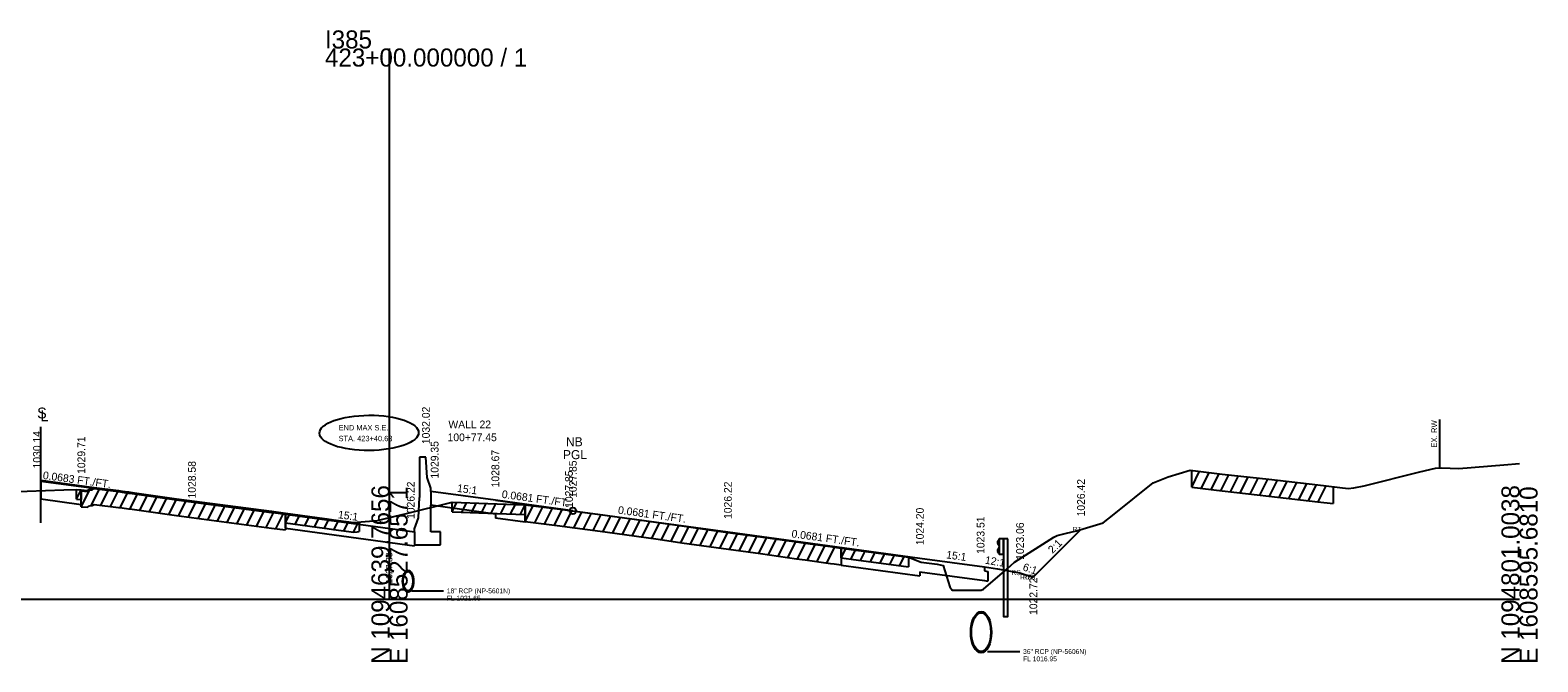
# Model space of a CAD drawing. Extents: x -26 to 1614813, y -18 to 1100051.
# Drawn here: x 4119.3 to 4352.8, y 9490.3 to 9588.2 of the extents above; entities that cross this region are included whole.
import ezdxf

# ---------------------------------------------------------------- set-up
doc = ezdxf.new("R2010")
doc.units = 0
for name, color, linetype in [('RD_EX_Misc', 7, 'Continuous'), ('RD_GPK_XS_Cell', 7, 'Continuous'), ('RD_HY_TX1', 7, 'Continuous'), ('RD_Sketch1', 7, 'Continuous'), ('RD_Sketch10', 7, 'Continuous'), ('RD_XS_Base', 7, 'Continuous'), ('RD_XS_CurbFront', 7, 'Continuous'), ('RD_XS_EarthShd', 7, 'Continuous'), ('RD_XS_ExGround', 7, 'Continuous'), ('RD_XS_ExPaveRet', 7, 'Continuous'), ('RD_XS_ExRW', 7, 'Continuous'), ('RD_XS_GR', 7, 'Continuous'), ('RD_XS_MedBbase', 7, 'Continuous'), ('RD_XS_MedBWall', 7, 'Continuous'), ('RD_XS_Milling', 7, 'Continuous'), ('RD_XS_Pave', 7, 'Continuous'), ('RD_XS_PaveOvlay', 7, 'Continuous'), ('RD_XS_PaveShd', 7, 'Continuous'), ('RD_XS_Pipe', 7, 'Continuous'), ('RD_XS_TieSlope', 7, 'Continuous'), ('RD_XS_TX_Elev_PR', 7, 'Continuous'), ('RD_XS_TX_MatchLine', 7, 'Continuous'), ('RD_XS_TX_Misc', 7, 'Continuous'), ('RD_XS_TX_Notes', 7, 'Continuous'), ('RD_XS_TX_ShdSlope', 7, 'Continuous'), ('RD_XS_TX_Slope', 7, 'Continuous')]:
    doc.layers.add(name, color=color, linetype=linetype)

msp = doc.modelspace()

# ---------------------------------------------------------------- linework, layer by layer
at = {"layer": 'RD_EX_Misc'}
for p, q in [((4126.52, 9515.51), (4126.52, 9517.01)), ((4126.52, 9515.51), (4127.27, 9515.44)), ((4127.27, 9516.94), (4127.27, 9515.44)), ((4127.27, 9515.44), (4127.27, 9515.44)), ((4184.7, 9513.57), (4184.7, 9515.07)), ((4158.87, 9511.85), (4158.87, 9513.35)), ((4184.7, 9513.57), (4190.23, 9513.35)), ((4190.23, 9513.35), (4196.01, 9513.15)), ((4196.01, 9514.65), (4196.01, 9513.15)), ((4158.87, 9511.85), (4164.93, 9511.02)), ((4158.87, 9511.85), (4158.87, 9511.85)), ((4164.93, 9511.02), (4165.32, 9510.96)), ((4165.32, 9510.96), (4166.34, 9510.82)), ((4166.34, 9510.82), (4169.48, 9510.39)), ((4169.48, 9510.39), (4170, 9510.45)), ((4170, 9510.45), (4170.31, 9510.48)), ((4170.31, 9511.98), (4170.31, 9510.48)), ((4244.95, 9506.43), (4244.95, 9507.93)), ((4244.95, 9506.43), (4246.49, 9506.22)), ((4244.95, 9506.43), (4244.95, 9506.43)), ((4246.49, 9506.22), (4255.36, 9505.01)), ((4255.36, 9506.51), (4255.36, 9505.01)), ((4255.36, 9505.01), (4255.36, 9505.01))]:
    msp.add_line(p, q, dxfattribs=at)
at = {"layer": 'RD_GPK_XS_Cell'}
for p, q in [((4175, 9500), (4175, 9585.33)), ((4000, 9500), (4175, 9500)), ((4175, 9500), (4350, 9500))]:
    msp.add_line(p, q, dxfattribs=at)
at = {"layer": 'RD_Sketch1'}
for p, q in [((4126.52, 9515.51), (4127.24, 9516.95)), ((4184.7, 9513.57), (4185.44, 9515.04)), ((4186.21, 9513.51), (4186.95, 9514.98)), ((4187.72, 9513.45), (4188.46, 9514.92)), ((4158.87, 9511.85), (4159.58, 9513.26)), ((4160.38, 9511.64), (4161.09, 9513.05)), ((4161.89, 9511.44), (4162.6, 9512.84)), ((4163.4, 9511.23), (4164.1, 9512.63)), ((4189.23, 9513.39), (4189.97, 9514.86)), ((4190.74, 9513.33), (4191.48, 9514.81)), ((4192.24, 9513.28), (4192.98, 9514.76)), ((4193.75, 9513.23), (4194.49, 9514.7)), ((4195.26, 9513.18), (4196, 9514.65)), ((4164.91, 9511.02), (4165.61, 9512.42)), ((4166.41, 9510.81), (4167.12, 9512.21)), ((4167.92, 9510.6), (4168.63, 9512)), ((4169.43, 9510.39), (4170.22, 9511.97)), ((4244.95, 9506.43), (4245.65, 9507.83)), ((4246.45, 9506.23), (4247.16, 9507.63)), ((4247.96, 9506.02), (4248.67, 9507.43)), ((4249.47, 9505.82), (4250.18, 9507.22)), ((4250.98, 9505.61), (4251.68, 9507.01)), ((4252.49, 9505.4), (4253.19, 9506.81)), ((4253.99, 9505.2), (4254.7, 9506.6))]:
    msp.add_line(p, q, dxfattribs=at)
at = {"layer": 'RD_Sketch10'}
for p, q in [((4121, 9518.45), (4145, 9515.17)), ((4145, 9515.17), (4157, 9513.53)), ((4191.39, 9515.34), (4203.39, 9513.71)), ((4203.39, 9513.71), (4227.4, 9510.44)), ((4227.4, 9510.44), (4251.4, 9507.17))]:
    msp.add_line(p, q, dxfattribs=at)
at = {"layer": 'RD_XS_Base'}
for p, q in [((4121, 9518.27), (4121, 9515.5)), ((4127.27, 9514.64), (4121, 9515.5)), ((4158.87, 9511.03), (4158.87, 9513.17)), ((4191.39, 9513.21), (4181.39, 9514.57)), ((4191.39, 9513.21), (4191.39, 9512.57)), ((4196.01, 9511.94), (4191.39, 9512.57)), ((4196.01, 9514.65), (4200.98, 9514.01)), ((4196.01, 9514.65), (4196.01, 9511.94)), ((4200.98, 9514.01), (4203.39, 9513.69)), ((4203.39, 9513.69), (4208.38, 9513.04)), ((4208.38, 9513.04), (4216.61, 9511.89)), ((4158.87, 9511.03), (4178.89, 9508.3)), ((4216.61, 9511.89), (4220.28, 9511.36)), ((4220.28, 9511.36), (4225.61, 9510.61)), ((4225.61, 9510.61), (4227.4, 9510.37)), ((4227.4, 9510.37), (4232.44, 9509.67)), ((4232.44, 9509.67), (4238.02, 9508.88)), ((4238.02, 9508.88), (4239.36, 9508.7)), ((4239.36, 9508.7), (4243.32, 9508.16)), ((4243.32, 9508.16), (4243.84, 9508.09)), ((4243.84, 9508.09), (4244.95, 9507.93)), ((4244.95, 9507.93), (4244.95, 9505.27)), ((4244.95, 9505.27), (4257.14, 9503.61)), ((4257.14, 9504.26), (4267.14, 9502.89)), ((4257.14, 9504.26), (4257.14, 9503.61)), ((4267.14, 9505.03), (4267.14, 9504.39)), ((4267.14, 9504.39), (4267.64, 9504.32)), ((4267.64, 9504.32), (4267.64, 9502.82)), ((4267.14, 9502.89), (4267.64, 9502.82))]:
    msp.add_line(p, q, dxfattribs=at)
at = {"layer": 'RD_XS_CurbFront'}
for p, q in [((4181.39, 9516.71), (4181.39, 9514.57)), ((4178.89, 9510.44), (4178.89, 9508.44))]:
    msp.add_line(p, q, dxfattribs=at)
at = {"layer": 'RD_XS_EarthShd'}
for p, q in [((4267.14, 9505.03), (4269.14, 9504.7)), ((4269.14, 9504.7), (4272.64, 9504.11))]:
    msp.add_line(p, q, dxfattribs=at)
at = {"layer": 'RD_XS_ExGround'}
msp.add_lwpolyline([(4116.06, 9516.66), (4124.54, 9516.94), (4126.52, 9517.01), (4127.27, 9516.94), (4128.22, 9516.85), (4128.56, 9517.07), (4128.97, 9517.12), (4129.26, 9517.31), (4133.03, 9516.84), (4133.61, 9516.77), (4134.57, 9516.63), (4135.14, 9516.54), (4142.02, 9515.56), (4156.71, 9513.63), (4158.87, 9513.35), (4164.93, 9512.52), (4165.32, 9512.46), (4166.34, 9512.32), (4169.48, 9511.89), (4170, 9511.95), (4173.13, 9512.21), (4175, 9512.67), (4177.41, 9513.26), (4184.69, 9515.07), (4190.23, 9514.85), (4196.01, 9514.65), (4200.98, 9514.01), (4208.38, 9513.04), (4216.61, 9511.89), (4220.28, 9511.36), (4225.61, 9510.61), (4232.44, 9509.67), (4238.02, 9508.88), (4239.36, 9508.7), (4243.32, 9508.16), (4243.84, 9508.09), (4244.95, 9507.93), (4246.49, 9507.72), (4255.36, 9506.51), (4257.31, 9505.73), (4259.82, 9505.44), (4260.76, 9505.22), (4261.75, 9501.94), (4262.13, 9501.43), (4266.63, 9501.43), (4266.97, 9501.55), (4270.68, 9504.73), (4271.8, 9505.74), (4277.9, 9509.62), (4278.39, 9509.89), (4279.86, 9510.22), (4281.38, 9510.63), (4285.5, 9511.83), (4287.25, 9513.2), (4293.28, 9518.02), (4295.57, 9518.95), (4299.02, 9520.01), (4303.97, 9519.38), (4311.18, 9518.59), (4318.75, 9517.71), (4323.48, 9517.16), (4324.36, 9517.29), (4325.96, 9517.57), (4334.56, 9519.72), (4336.98, 9520.3), (4337.91, 9520.38), (4340.59, 9520.24), (4347.57, 9520.85), (4350, 9521.05)], dxfattribs=at)
at = {"layer": 'RD_XS_ExPaveRet'}
for p, q in [((4299.23, 9517.38), (4299.23, 9519.98)), ((4299.23, 9517.38), (4300.46, 9519.83)), ((4300.74, 9517.19), (4301.96, 9519.64)), ((4299.23, 9517.38), (4303.97, 9516.78)), ((4302.24, 9517), (4303.47, 9519.45)), ((4303.75, 9516.81), (4304.99, 9519.27)), ((4305.26, 9516.64), (4306.49, 9519.11)), ((4306.76, 9516.48), (4308, 9518.94)), ((4308.27, 9516.31), (4309.51, 9518.78)), ((4309.78, 9516.15), (4311.01, 9518.61)), ((4311.28, 9515.98), (4312.52, 9518.44)), ((4312.79, 9515.8), (4314.02, 9518.26)), ((4314.3, 9515.63), (4315.53, 9518.08)), ((4315.8, 9515.45), (4317.04, 9517.91)), ((4317.31, 9515.28), (4318.55, 9517.73)), ((4318.82, 9515.1), (4320.05, 9517.56)), ((4321.15, 9517.43), (4321.15, 9514.83)), ((4127.27, 9514.34), (4128.65, 9517.08)), ((4127.27, 9514.34), (4127.27, 9516.94)), ((4128.78, 9514.5), (4130.14, 9517.2)), ((4130.29, 9514.58), (4131.52, 9517.03)), ((4131.8, 9514.4), (4133.02, 9516.84)), ((4133.3, 9514.21), (4134.52, 9516.63)), ((4134.81, 9513.99), (4136.03, 9516.42)), ((4136.32, 9513.78), (4137.53, 9516.2)), ((4137.82, 9513.56), (4139.04, 9515.99)), ((4139.33, 9513.34), (4140.55, 9515.77)), ((4140.84, 9513.13), (4142.06, 9515.56)), ((4142.34, 9512.92), (4143.57, 9515.36)), ((4143.85, 9512.72), (4145.08, 9515.16)), ((4145.36, 9512.52), (4146.58, 9514.96)), ((4303.97, 9516.78), (4311.18, 9515.99)), ((4311.18, 9515.99), (4318.75, 9515.11)), ((4318.75, 9515.11), (4321.15, 9514.83)), ((4127.27, 9514.34), (4128.22, 9514.25)), ((4128.22, 9514.25), (4128.56, 9514.47)), ((4128.56, 9514.47), (4128.97, 9514.52)), ((4128.97, 9514.52), (4129.26, 9514.71)), ((4129.26, 9514.71), (4133.03, 9514.24)), ((4133.03, 9514.24), (4133.61, 9514.17)), ((4133.61, 9514.17), (4134.57, 9514.03)), ((4134.57, 9514.03), (4135.14, 9513.94)), ((4135.14, 9513.94), (4142.02, 9512.96)), ((4142.02, 9512.96), (4156.71, 9511.03)), ((4146.86, 9512.32), (4148.09, 9514.76)), ((4148.37, 9512.13), (4149.6, 9514.56)), ((4149.88, 9511.93), (4151.1, 9514.37)), ((4151.38, 9511.73), (4152.61, 9514.17)), ((4152.89, 9511.53), (4154.12, 9513.97)), ((4154.4, 9511.33), (4155.62, 9513.77)), ((4155.91, 9511.14), (4157.13, 9513.58)), ((4157.41, 9510.94), (4158.64, 9513.38)), ((4158.87, 9513.35), (4158.87, 9510.75)), ((4196.01, 9512.05), (4196.01, 9514.65)), ((4196.01, 9512.05), (4197.24, 9514.49)), ((4197.52, 9511.86), (4198.74, 9514.3)), ((4199.02, 9511.66), (4200.25, 9514.1)), ((4200.53, 9511.47), (4201.76, 9513.91)), ((4202.04, 9511.27), (4203.26, 9513.71)), ((4203.54, 9511.07), (4204.77, 9513.51)), ((4205.05, 9510.88), (4206.28, 9513.32)), ((4206.56, 9510.68), (4207.78, 9513.12)), ((4208.07, 9510.49), (4209.29, 9512.92)), ((4209.57, 9510.28), (4210.79, 9512.71)), ((4156.71, 9511.03), (4158.87, 9510.75)), ((4196.01, 9512.05), (4200.98, 9511.41)), ((4200.98, 9511.41), (4208.38, 9510.44)), ((4208.38, 9510.44), (4216.61, 9509.29)), ((4211.08, 9510.07), (4212.3, 9512.49)), ((4212.59, 9509.85), (4213.81, 9512.28)), ((4214.09, 9509.64), (4215.31, 9512.07)), ((4215.6, 9509.43), (4216.82, 9511.86)), ((4217.11, 9509.22), (4218.32, 9511.64)), ((4218.61, 9509), (4219.83, 9511.43)), ((4220.12, 9508.78), (4221.34, 9511.21)), ((4221.63, 9508.57), (4222.85, 9511)), ((4223.13, 9508.36), (4224.35, 9510.79)), ((4224.64, 9508.15), (4225.86, 9510.58)), ((4226.15, 9507.94), (4227.37, 9510.37)), ((4216.61, 9509.29), (4220.28, 9508.76)), ((4220.28, 9508.76), (4225.61, 9508.01)), ((4225.61, 9508.01), (4232.44, 9507.07)), ((4227.65, 9507.73), (4228.88, 9510.16)), ((4229.16, 9507.52), (4230.38, 9509.95)), ((4230.67, 9507.31), (4231.89, 9509.74)), ((4232.18, 9507.1), (4233.4, 9509.53)), ((4233.68, 9506.89), (4234.9, 9509.32)), ((4235.19, 9506.68), (4236.41, 9509.11)), ((4236.7, 9506.47), (4237.92, 9508.9)), ((4238.2, 9506.26), (4239.43, 9508.69)), ((4239.71, 9506.05), (4240.93, 9508.48)), ((4241.22, 9505.84), (4242.44, 9508.28)), ((4242.72, 9505.64), (4243.95, 9508.07)), ((4244.95, 9507.93), (4244.95, 9505.33)), ((4232.44, 9507.07), (4238.02, 9506.28)), ((4238.02, 9506.28), (4239.36, 9506.1)), ((4239.36, 9506.1), (4243.32, 9505.56)), ((4243.32, 9505.56), (4243.84, 9505.49)), ((4243.84, 9505.49), (4244.95, 9505.33))]:
    msp.add_line(p, q, dxfattribs=at)
at = {"layer": 'RD_XS_ExRW'}
msp.add_line((4337.6, 9527.87), (4337.6, 9520.36), dxfattribs=at)
at = {"layer": 'RD_XS_GR'}
for p, q in [((4269.17, 9508.93), (4269.32, 9509.16)), ((4269.17, 9508.69), (4269.38, 9508.37)), ((4269.17, 9507.66), (4269.38, 9507.98)), ((4269.41, 9509.2), (4269.33, 9509.17)), ((4269.17, 9507.41), (4269.32, 9507.19)), ((4269.41, 9507.15), (4269.33, 9507.18))]:
    msp.add_line(p, q, dxfattribs=at)
for points in [[(4270.08, 9509.34), (4269.41, 9509.34), (4269.41, 9507.01), (4270.08, 9507.01)], [(4270.74, 9509.34), (4270.08, 9509.34), (4270.08, 9497.34), (4270.74, 9497.34)]]:
    msp.add_lwpolyline(points, close=True, dxfattribs=at)
for centre, major_axis, start_param, end_param in [((4269.22, 9508.81), (0, -0.156), 3.787686, 5.637551), ((4269.34, 9509.11), (0, 0.0626), 0.174533, 0.6458), ((4269.33, 9508.25), (0, 0.156), 4.712389, 5.637385), ((4269.33, 9508.1), (0, -0.156), 0.6458, 1.570796), ((4269.22, 9507.54), (0, -0.156), 3.787227, 5.637092), ((4269.34, 9507.24), (0, -0.0626), 5.637385, 6.108652)]:
    msp.add_ellipse(centre, major_axis=major_axis, ratio=0.5, start_param=start_param, end_param=end_param, dxfattribs=at)
at = {"layer": 'RD_XS_MedBbase'}
for p, q in [((4181.39, 9510.44), (4181.39, 9514.57)), ((4182.89, 9510.44), (4181.39, 9510.44)), ((4182.89, 9508.44), (4182.89, 9510.44)), ((4178.89, 9508.44), (4182.89, 9508.44)), ((4178.89, 9508.44), (4178.89, 9508.3))]:
    msp.add_line(p, q, dxfattribs=at)
at = {"layer": 'RD_XS_MedBWall'}
for p, q in [((4179.64, 9522.04), (4179.64, 9515.77)), ((4180.64, 9522.04), (4179.64, 9522.04)), ((4180.81, 9518.87), (4180.64, 9522.04)), ((4181.39, 9517.21), (4180.81, 9518.87)), ((4181.39, 9516.71), (4181.39, 9517.21)), ((4179.48, 9512.6), (4179.64, 9515.77)), ((4178.89, 9510.94), (4179.48, 9512.6)), ((4178.89, 9510.44), (4178.89, 9510.94))]:
    msp.add_line(p, q, dxfattribs=at)
at = {"layer": 'RD_XS_Milling'}
for p, q in [((4127.27, 9516.94), (4127.27, 9516.78)), ((4127.27, 9516.78), (4128.22, 9516.69)), ((4128.22, 9516.69), (4128.56, 9516.91)), ((4128.56, 9516.91), (4128.97, 9516.96)), ((4128.97, 9516.96), (4129.26, 9517.15)), ((4129.26, 9517.15), (4133.03, 9516.68)), ((4133.03, 9516.68), (4133.61, 9516.6)), ((4133.61, 9516.6), (4134.57, 9516.46)), ((4134.57, 9516.46), (4135.14, 9516.38)), ((4135.14, 9516.38), (4142.02, 9515.39)), ((4142.02, 9515.39), (4145, 9515)), ((4145, 9515.17), (4145, 9515)), ((4145, 9515), (4156.71, 9513.46)), ((4156.71, 9513.46), (4157, 9513.43)), ((4157, 9513.59), (4157, 9513.43))]:
    msp.add_line(p, q, dxfattribs=at)
at = {"layer": 'RD_XS_Pave'}
for p, q in [((4127.27, 9517.42), (4121, 9518.27)), ((4129.26, 9517.15), (4127.27, 9517.42)), ((4203.39, 9513.71), (4191.39, 9515.34)), ((4203.39, 9513.71), (4227.4, 9510.44)), ((4227.4, 9510.44), (4257.14, 9506.39))]:
    msp.add_line(p, q, dxfattribs=at)
at = {"layer": 'RD_XS_PaveOvlay'}
for p, q in [((4128.97, 9517.12), (4129.26, 9517.31)), ((4129.26, 9517.31), (4133.03, 9516.84)), ((4127.27, 9516.94), (4128.22, 9516.85)), ((4127.27, 9516.94), (4127.27, 9516.78)), ((4128.22, 9516.85), (4128.56, 9517.07)), ((4128.56, 9517.07), (4128.97, 9517.12)), ((4133.03, 9516.84), (4133.61, 9516.77)), ((4133.61, 9516.77), (4134.57, 9516.63)), ((4134.57, 9516.63), (4135.14, 9516.54)), ((4135.14, 9516.54), (4142.02, 9515.56)), ((4142.02, 9515.56), (4145, 9515.17)), ((4145, 9515.17), (4156.71, 9513.63)), ((4156.71, 9513.63), (4157, 9513.59)), ((4157, 9513.59), (4157, 9513.43))]:
    msp.add_line(p, q, dxfattribs=at)
at = {"layer": 'RD_XS_PaveShd'}
for p, q in [((4191.39, 9515.34), (4181.39, 9516.71)), ((4157, 9513.43), (4178.89, 9510.44)), ((4257.14, 9506.39), (4267.14, 9505.03))]:
    msp.add_line(p, q, dxfattribs=at)
at = {"layer": 'RD_XS_Pipe'}
for p, q in [((4178.38, 9501.3), (4183.38, 9501.3)), ((4267.62, 9491.9), (4272.62, 9491.9))]:
    msp.add_line(p, q, dxfattribs=at)
for centre, major_axis in [((4177.88, 9502.8), (0, 1.7)), ((4177.88, 9502.8), (0, 1.5)), ((4266.62, 9494.9), (0, 3.2)), ((4266.62, 9494.9), (0, 3))]:
    msp.add_ellipse(centre, major_axis=major_axis, ratio=0.5, dxfattribs=at)
at = {"layer": 'RD_XS_TieSlope'}
for p, q in [((4274.66, 9503.44), (4282.09, 9510.84)), ((4272.64, 9504.11), (4274.66, 9503.44))]:
    msp.add_line(p, q, dxfattribs=at)
at = {"layer": 'RD_XS_TX_MatchLine'}
for p, q in [((4121, 9516.82), (4121, 9526.71)), ((4121, 9511.82), (4121, 9516.82))]:
    msp.add_line(p, q, dxfattribs=at)
at = {"layer": 'RD_XS_TX_Misc'}
msp.add_circle((4203.39, 9513.71), 0.5, dxfattribs=at)
at = {"layer": 'RD_XS_TX_Notes'}
msp.add_ellipse((4171.83, 9525.78), major_axis=(7.68, 0.05), ratio=0.355189, dxfattribs=at)

# ---------------------------------------------------------------- texts
at = {"layer": 'RD_GPK_XS_Cell'}
for s, p in [('I385', (4165, 9585.33)), ('423+00.000000 / 1', (4165, 9582.53))]:
    msp.add_text(s, height=2.8, dxfattribs=at).set_placement(p)
for s, p in [('N 1094639.7656', (4175, 9490)), ('E 1608527.6571', (4177.8, 9490)), ('N 1094801.0038', (4350, 9490)), ('E 1608595.6810', (4352.8, 9490))]:
    msp.add_text(s, height=2.8, rotation=90, dxfattribs=at).set_placement(p)
at = {"layer": 'RD_HY_TX1'}
for s, p in [('RT', (4280.78, 9510.46)), ('RS', (4271.33, 9503.74)), ('RD2', (4272.67, 9503.07)), ('RD1', (4273.05, 9503.07))]:
    msp.add_text(s, height=0.75, dxfattribs=at).set_placement(p)
at = {"layer": 'RD_Sketch10'}
for s, p in [(' 1028.58', (4145, 9515.17)), (' 1027.85', (4203.39, 9513.71))]:
    msp.add_text(s, height=1.2, rotation=90, dxfattribs=at).set_placement(p)
at = {"layer": 'RD_XS_ExGround'}
msp.add_text('1027.33', height=1, rotation=90, dxfattribs=at).set_placement((4175.44, 9502.43))
at = {"layer": 'RD_XS_ExRW'}
msp.add_text('EX. RW', height=0.9, rotation=90, dxfattribs=at).set_placement((4337.24, 9523.47))
at = {"layer": 'RD_XS_Pipe'}
for s, p in [('18" RCP (NP-5601N)', (4183.88, 9500.93)), ('FL 1021.65', (4183.88, 9499.8)), ('36" RCP (NP-5606N)', (4273.12, 9491.53)), ('FL 1016.95', (4273.12, 9490.4))]:
    msp.add_text(s, height=0.75, dxfattribs=at).set_placement(p)
at = {"layer": 'RD_XS_TX_Elev_PR'}
for s, p in [('1032.02', (4181.24, 9524.04)), ('1030.14', (4121, 9520.27)), ('1029.71', (4127.87, 9519.42)), ('1029.35', (4182.59, 9518.71)), ('1028.67', (4191.99, 9517.34)), ('1027.85', (4203.99, 9515.71)), ('1026.22', (4178.89, 9512.44)), ('1026.22', (4228, 9512.44)), ('1026.42', (4282.69, 9512.84)), ('1024.20', (4257.74, 9508.39)), ('1023.51', (4267.14, 9507.03)), ('1023.06', (4273.24, 9506.11)), ('1022.72', (4275.31, 9497.57))]:
    msp.add_text(s, height=1.2, rotation=90, dxfattribs=at).set_placement(p)
at = {"layer": 'RD_XS_TX_MatchLine'}
for s, p in [('S', (4120.42, 9528.02)), ('L', (4120.93, 9527.59))]:
    msp.add_text(s, height=1.68, dxfattribs=at).set_placement(p)
at = {"layer": 'RD_XS_TX_Misc'}
for s, height, p in [('WALL 22', 1.2, (4184.12, 9526.49)), ('100+77.45', 1.2, (4183.99, 9524.49)), ('NB', 1.4, (4202.32, 9523.71)), ('PGL', 1.4, (4201.85, 9521.71))]:
    msp.add_text(s, height=height, dxfattribs=at).set_placement(p)
at = {"layer": 'RD_XS_TX_Notes'}
for s, p in [('END MAX S.E. ', (4167.11, 9526.16)), ('STA. 423+40.63', (4167.11, 9524.49))]:
    msp.add_text(s, height=0.8333, dxfattribs=at).set_placement(p)
at = {"layer": 'RD_XS_TX_ShdSlope'}
for s, rotation, p in [('15:1', 352.2443, (4185.41, 9516.66)), ('15:1', 352.2215, (4166.97, 9512.57)), ('15:1', 352.2454, (4261.16, 9506.35)), ('12:1', 350.5377, (4267.15, 9505.53))]:
    msp.add_text(s, height=1.2, rotation=rotation, dxfattribs=at).set_placement(p)
at = {"layer": 'RD_XS_TX_Slope'}
for s, rotation, p in [('0.0683 FT./FT.', 352.2215, (4121.26, 9518.65)), ('0.0681 FT./FT.', 352.2443, (4192.33, 9515.72)), ('0.0681 FT./FT.', 352.2448, (4210.33, 9513.27)), ('0.0681 FT./FT.', 352.2454, (4237.2, 9509.61)), ('2:1', 44.8634, (4277.69, 9507.01)), ('6:1', 341.6469, (4272.97, 9504.51))]:
    msp.add_text(s, height=1.2, rotation=rotation, dxfattribs=at).set_placement(p)

doc.saveas('drawing.dxf')
